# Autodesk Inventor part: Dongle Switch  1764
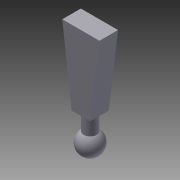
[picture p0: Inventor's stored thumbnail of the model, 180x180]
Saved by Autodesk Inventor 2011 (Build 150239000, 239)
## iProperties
Created: 2010-01
Part Number: Dongle Switch  1764
Document SubType Name: Modeling
Designer: jgehrig
Density: 1 g/cm^3
Author: jgehrig
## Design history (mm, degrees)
sketch "Sketch1"
  geometry: L1 (-6.921, 27.03)-(-1.841, 27.03); L2 (-3.111, 16.87)-(-5.651, 16.87); L3 (-6.921, 27.03)-(-5.651, 16.87); L4 (-3.111, 16.87)-(-1.841, 27.03); 1 further point
  constraints: 8 end point, 1 horizontal, 1 parallel
  dimensions: "d0" = 5.08 distance of L1.start L1.end; "d1" = 2.54 distance of L2.start L2.end; "d2" = 10.16 distance between parallel lines of L2 L1; "d3" = 1.27 horizontal distance of L1.start L2.end
extrude "Extrusion1" new body sketch "Sketch1" distance "d4" = 2.54; taper "d5" = 0 deg
workplane "Work Plane1"
sketch "Sketch2"
  geometry: L1 (-3.111, 16.87)-(-5.651, 16.87) reference; L2 (-4.381, 16.87)-(-4.381, 14.33); L3 (-3.492, 16.87)-(-3.492, 14.33); L4 (-4.381, 14.33)-(-3.492, 14.33); L5 (-4.381, 16.87)-(-3.492, 16.87); L6 (-4.381, 14.33)-(-4.381, 11.536); L7 (-4.381, 16.87)-(-3.492, 16.87); L8 (-3.492, 16.87)-(-4.381, 16.87); L9 (-4.381, 16.87)-(-3.492, 16.87); L10 (-3.492, 16.87)-(-3.492, 14.33); L11 (-3.492, 14.33)-(-4.381, 14.33); L12 (-4.381, 14.33)-(-4.381, 16.87); A1 r 1.587 centre (-4.381, 13.124) between (-4.381, 11.536) and (-4.381, 14.711); 1 further point
  constraints: 22 end point, 5 perpendicular, 3 parallel, 2 collinear, 2 point on circle, 2 point on line, 1 centre point, 1 horizontal, 1 midpoint
  dimensions: "d7" = 2.54 distance of L2.start L2.end; "d8" = 0.889 distance of L2.end L3.end; "d9" = 0 distance from line of L6 A1.centre; "d10" = 0.381 distance of A1.end L2.end; "d11" = 3.175 distance of L6.end A1.end
revolve "Revolution1" sketch "Sketch2" stored, may be unused: angle "d12" = 90 deg
body "Solid1"
other parameters: "d6" = 1.27
